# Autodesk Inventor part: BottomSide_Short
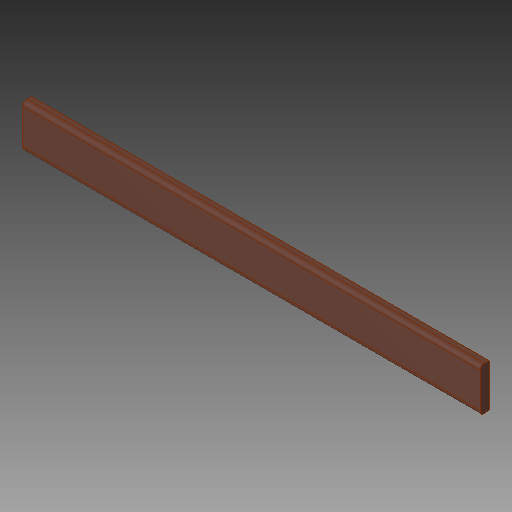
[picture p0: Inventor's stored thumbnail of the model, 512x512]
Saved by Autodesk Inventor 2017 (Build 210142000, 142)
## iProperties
Created: 2017-05
Part Number: BottomSide_Short
Material: Generic
Document SubType Name: Modeling
Designer: Savy
Density: 1 g/cm^3
Appearance: Default
Mass: 537.374 g
Surface Area: 1016.98 cm^2
Volume: 537.374 cm^3
Author: Savy
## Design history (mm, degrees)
feature "SOLID1"
body "Solid1"
